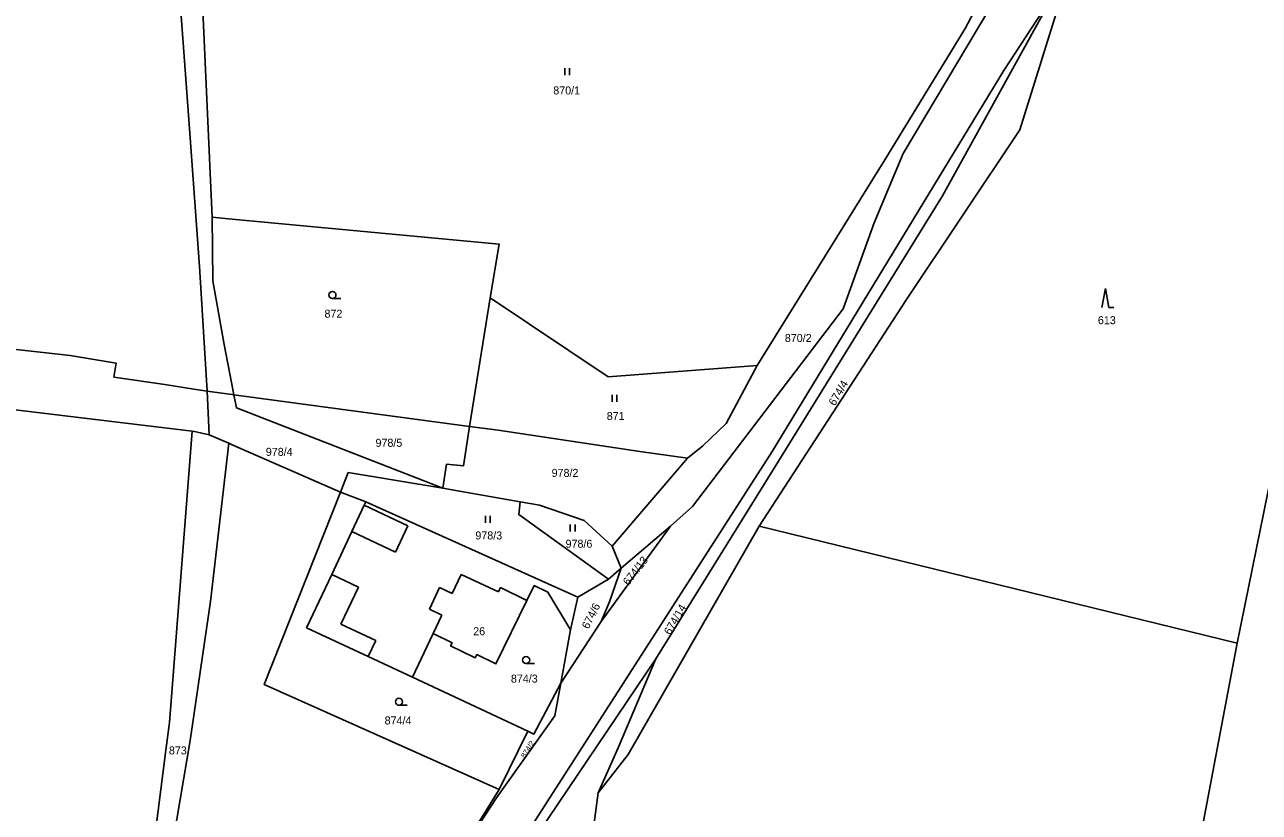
# Model space of a CAD drawing. Extents: x -7483133 to -743907, y -11317770 to -1129777.
# Drawn here: x -747219.6 to -746957.4, y -1133122.3 to -1132955.1 of the extents above; entities that cross this region are included whole.
import ezdxf

# ---------------------------------------------------------------- set-up
doc = ezdxf.new("R2010")
doc.units = 0
for name, color, linetype in [('Hranice parcel', 7, 'Continuous'), ('Parcelní čísla', 7, 'Continuous'), ('Vnitřní kresba', 7, 'Continuous'), ('Značky kultur', 7, 'Continuous')]:
    doc.layers.add(name, color=color, linetype=linetype)

msp = doc.modelspace()

# ---------------------------------------------------------------- linework, layer by layer
at = {"layer": 'Hranice parcel'}
for p, q in [((-747120.7, -1133013.08), (-747125.15, -1133040.39)), ((-747180.38, -1133042.21), (-747180.82, -1133032.94)), ((-747175.17, -1133033.7), (-747125.15, -1133040.39)), ((-747176.22, -1133043.98), (-747180.38, -1133042.21)), ((-747078.82, -1133047.16), (-747094.83, -1133065.8)), ((-747147.13, -1133056.42), (-747152.49, -1133054.34)), ((-747147.13, -1133056.42), (-747147.46, -1133057.1)), ((-747102.11, -1133076.62), (-747147.13, -1133056.42)), ((-747097.19, -1133081.83), (-747082.43, -1133061.55)), ((-747092.94, -1133070.51), (-747082.43, -1133061.55)), ((-747092.94, -1133070.51), (-747082.43, -1133061.55)), ((-747063.59, -1133061.56), (-746962.09, -1133086.41)), ((-747094.83, -1133065.8), (-747092.94, -1133070.51)), ((-747092.94, -1133070.51), (-747095.6, -1133072.8)), ((-747092.94, -1133070.51), (-747095.6, -1133072.8)), ((-747102.11, -1133076.62), (-747095.6, -1133072.8)), ((-747102.11, -1133076.62), (-747095.6, -1133072.8)), ((-747108.51, -1133075.58), (-747103.65, -1133083.61)), ((-747103.65, -1133083.61), (-747102.11, -1133076.62)), ((-747103.65, -1133083.61), (-747102.11, -1133076.62)), ((-747105.75, -1133094.93), (-747097.19, -1133081.83)), ((-747105.75, -1133094.93), (-747103.65, -1133083.61)), ((-747105.75, -1133094.93), (-747103.65, -1133083.61)), ((-747137.2, -1133093.67), (-747112.75, -1133105.11)), ((-747112.75, -1133105.11), (-747118.82, -1133117.5))]:
    msp.add_line(p, q, dxfattribs=at)
for points in [[(-747180.82, -1133032.94), (-747182.45, -1133006.42), (-747183.17, -1132996.67), (-747184.46, -1132979.1), (-747185.65, -1132962.8), (-747189.83, -1132906.57), (-747193.53, -1132877.19), (-747202.48, -1132826.92), (-747220.56, -1132784.45)], [(-747184.42, -1132898.81), (-747181.92, -1132948.88), (-747179.76, -1132996)], [(-747064.03, -1133027.44), (-747036.92, -1132983.8), (-747019.89, -1132955.94), (-747011.03, -1132939.22)], [(-747000.79, -1132948.22), (-747011.62, -1132964.83), (-747060.85, -1133045.72), (-747119.18, -1133136.56)], [(-747000.79, -1132948.22), (-747024.69, -1132991.47), (-747060.4, -1133049.29), (-747085.54, -1133089.77)], [(-747063.59, -1133061.56), (-747032.47, -1133013.67), (-747008.28, -1132977.41), (-746999.22, -1132948.35)], [(-747082.43, -1133061.55), (-747077.79, -1133057.43), (-747045.76, -1133015.45), (-747039.19, -1132997.18), (-747033.02, -1132982.46), (-747014.63, -1132951.61)], [(-747082.43, -1133061.55), (-747077.79, -1133057.43), (-747045.76, -1133015.45), (-747039.19, -1132997.18), (-747033.02, -1132982.46), (-747014.63, -1132951.61)], [(-746962.09, -1133086.41), (-746954.85, -1133050.6), (-746943.29, -1132988.79), (-746934.3, -1132970.8), (-746930.34, -1132957.34)], [(-747200.64, -1133029.94), (-747200.15, -1133026.98), (-747209.89, -1133025.38), (-747221.38, -1133024.08), (-747276.48, -1133014.17), (-747452.96, -1132989.98)], [(-747179.76, -1132996), (-747176.3, -1132996.32), (-747118.84, -1133001.68), (-747120.7, -1133013.08)], [(-747179.76, -1132996), (-747179.59, -1133009.51), (-747177.2, -1133023.01), (-747175.67, -1133031.09), (-747175.17, -1133033.7)], [(-747183.98, -1133041.41), (-747321.44, -1133024.87), (-747460.68, -1133008.17)], [(-747120.7, -1133013.08), (-747095.67, -1133029.89), (-747064.03, -1133027.44)], [(-747064.03, -1133027.44), (-747070.64, -1133039.81), (-747075.57, -1133044.53), (-747078.82, -1133047.16)], [(-747180.82, -1133032.94), (-747183.64, -1133032.48), (-747189.84, -1133031.47), (-747200.64, -1133029.94)], [(-747180.82, -1133032.94), (-747175.62, -1133033.64), (-747175.17, -1133033.7)], [(-747130.75, -1133053.53), (-747174.63, -1133036.48), (-747175.17, -1133033.7)], [(-747125.15, -1133040.39), (-747126.38, -1133048.77), (-747129.99, -1133048.39), (-747130.75, -1133053.53)], [(-747125.15, -1133040.39), (-747119.06, -1133041.2), (-747088.98, -1133045.73), (-747078.82, -1133047.16)], [(-747183.98, -1133041.41), (-747188.86, -1133103.23), (-747189.61, -1133109.13), (-747192.87, -1133134.77), (-747198.76, -1133141.14), (-747218.29, -1133162.23), (-747260.55, -1133181.81), (-747256.49, -1133186.83), (-747216.5, -1133165.46), (-747200.93, -1133148.71), (-747189.41, -1133136.32), (-747184.44, -1133107.11), (-747180.1, -1133077.6), (-747176.22, -1133043.98)], [(-747180.38, -1133042.21), (-747183.52, -1133041.51), (-747183.98, -1133041.41)], [(-747152.49, -1133054.34), (-747175.49, -1133044.3), (-747176.22, -1133043.98)], [(-747130.75, -1133053.53), (-747150.85, -1133050.22), (-747152.49, -1133054.34)], [(-747130.75, -1133053.53), (-747127.26, -1133054.15), (-747114.33, -1133056.44)], [(-747152.49, -1133054.34), (-747168.72, -1133095.23), (-747118.82, -1133117.5)], [(-747095.6, -1133072.8), (-747114.67, -1133059.13), (-747114.33, -1133056.44)], [(-747114.33, -1133056.44), (-747110.23, -1133057.14), (-747100.75, -1133060.35), (-747094.83, -1133065.8)], [(-747147.46, -1133057.1), (-747150.13, -1133062.69), (-747154.38, -1133071.87), (-747159.7, -1133083.14), (-747146.66, -1133089.23), (-747137.2, -1133093.67)], [(-747097.81, -1133118.17), (-747091.42, -1133110.03), (-747063.59, -1133061.56)], [(-747097.19, -1133081.83), (-747095.41, -1133077.62), (-747092.94, -1133070.51)], [(-747137.2, -1133093.67), (-747132.86, -1133084.38), (-747128.81, -1133086.33), (-747129.13, -1133086.99), (-747123.91, -1133089.51), (-747123.59, -1133088.84), (-747119.5, -1133090.81), (-747112.93, -1133077.35), (-747111.4, -1133074.21), (-747108.51, -1133075.58)], [(-747052.72, -1133264.93), (-747008.18, -1133133.52), (-746971.22, -1133134.66), (-746962.09, -1133086.41)], [(-747085.54, -1133089.77), (-747112.51, -1133129.74), (-747115.94, -1133137.3), (-747116.37, -1133140.87)], [(-747097.81, -1133118.17), (-747093.53, -1133108.61), (-747085.54, -1133089.77)], [(-747135.6, -1133142.1), (-747130.21, -1133135.85), (-747119.4, -1133119.28), (-747107.03, -1133101.85), (-747105.75, -1133094.93)], [(-747135.6, -1133142.1), (-747130.21, -1133135.85), (-747119.4, -1133119.28), (-747107.03, -1133101.85), (-747105.75, -1133094.93)], [(-747105.75, -1133094.93), (-747111.48, -1133105.71), (-747112.75, -1133105.11)], [(-747118.82, -1133117.5), (-747125.61, -1133128.45), (-747135.6, -1133142.1)], [(-747097.78, -1133177.11), (-747099.68, -1133170.28), (-747101.53, -1133146.44), (-747097.81, -1133118.17)]]:
    msp.add_lwpolyline(points, dxfattribs=at)
at = {"layer": 'Vnitřní kresba'}
for p, q in [((-747147.46, -1133057.1), (-747138.24, -1133061.5)), ((-747138.24, -1133061.5), (-747140.83, -1133067.07)), ((-747140.83, -1133067.07), (-747150.13, -1133062.69)), ((-747148.7, -1133074.55), (-747154.38, -1133071.87)), ((-747126.86, -1133071.87), (-747128.77, -1133075.91)), ((-747118.97, -1133075.51), (-747126.86, -1133071.87)), ((-747148.7, -1133074.55), (-747152.41, -1133082.41)), ((-747131.49, -1133074.62), (-747133.64, -1133079.18)), ((-747128.77, -1133075.91), (-747131.49, -1133074.62)), ((-747118.97, -1133075.51), (-747118.53, -1133074.61)), ((-747112.93, -1133077.35), (-747118.53, -1133074.61)), ((-747133.64, -1133079.18), (-747130.98, -1133080.47)), ((-747152.41, -1133082.41), (-747145.03, -1133085.88)), ((-747130.98, -1133080.47), (-747132.86, -1133084.38)), ((-747145.03, -1133085.88), (-747146.66, -1133089.23))]:
    msp.add_line(p, q, dxfattribs=at)
at = {"layer": 'Značky kultur'}
for p, q in [((-747104.87, -1132965.85), (-747104.87, -1132964.35)), ((-747103.87, -1132965.85), (-747103.87, -1132964.35)), ((-746990.08, -1133011.15), (-746990.83, -1133015.15)), ((-746989.33, -1133015.15), (-746990.08, -1133011.15)), ((-747154.22, -1133013.25), (-747152.47, -1133013.25)), ((-746989.33, -1133015.15), (-746988.33, -1133015.15)), ((-747094.8, -1133035.2), (-747094.8, -1133033.7)), ((-747093.8, -1133035.2), (-747093.8, -1133033.7)), ((-747121.73, -1133060.86), (-747121.73, -1133059.36)), ((-747120.73, -1133060.86), (-747120.73, -1133059.36)), ((-747103.71, -1133062.74), (-747103.71, -1133061.24)), ((-747102.71, -1133062.74), (-747102.71, -1133061.24)), ((-747113.09, -1133090.76), (-747111.34, -1133090.76)), ((-747140.1, -1133099.61), (-747138.35, -1133099.61))]:
    msp.add_line(p, q, dxfattribs=at)
for centre in [(-747154.22, -1133012.5), (-747113.09, -1133090.01), (-747140.1, -1133098.86)]:
    msp.add_circle(centre, 0.75, dxfattribs=at)

# ---------------------------------------------------------------- texts
at = {"layer": 'Parcelní čísla'}
for s, p in [('870/1', (-747107.33, -1132969.92)), ('872', (-747155.91, -1133017.32)), ('613', (-746991.68, -1133018.7)), ('870/2', (-747058.16, -1133022.48)), ('871', (-747095.97, -1133039.04)), ('978/5', (-747145.08, -1133044.73)), ('978/4', (-747168.37, -1133046.65)), ('978/2', (-747107.68, -1133051.12)), ('978/3', (-747123.87, -1133064.4)), ('978/6', (-747104.72, -1133066.16)), ('26', (-747124.33, -1133084.74)), ('874/3', (-747116.33, -1133094.79)), ('874/4', (-747143.14, -1133103.68)), ('873', (-747188.95, -1133110.04))]:
    msp.add_text(s, height=1.7, dxfattribs=at).set_placement(p)
for s, height, rotation, p in [('674/4', 1.7, 59, (-747047.55, -1133036.17)), ('674/13', 1.7, 52, (-747091.37, -1133074.31)), ('674/6', 1.7, 63, (-747099.86, -1133083.56)), ('674/14', 1.7, 60, (-747082.48, -1133084.81)), ('874/2', 1.14, 58, (-747113.34, -1133110.93))]:
    msp.add_text(s, height=height, rotation=rotation, dxfattribs=at).set_placement(p)

doc.saveas('drawing.dxf')
